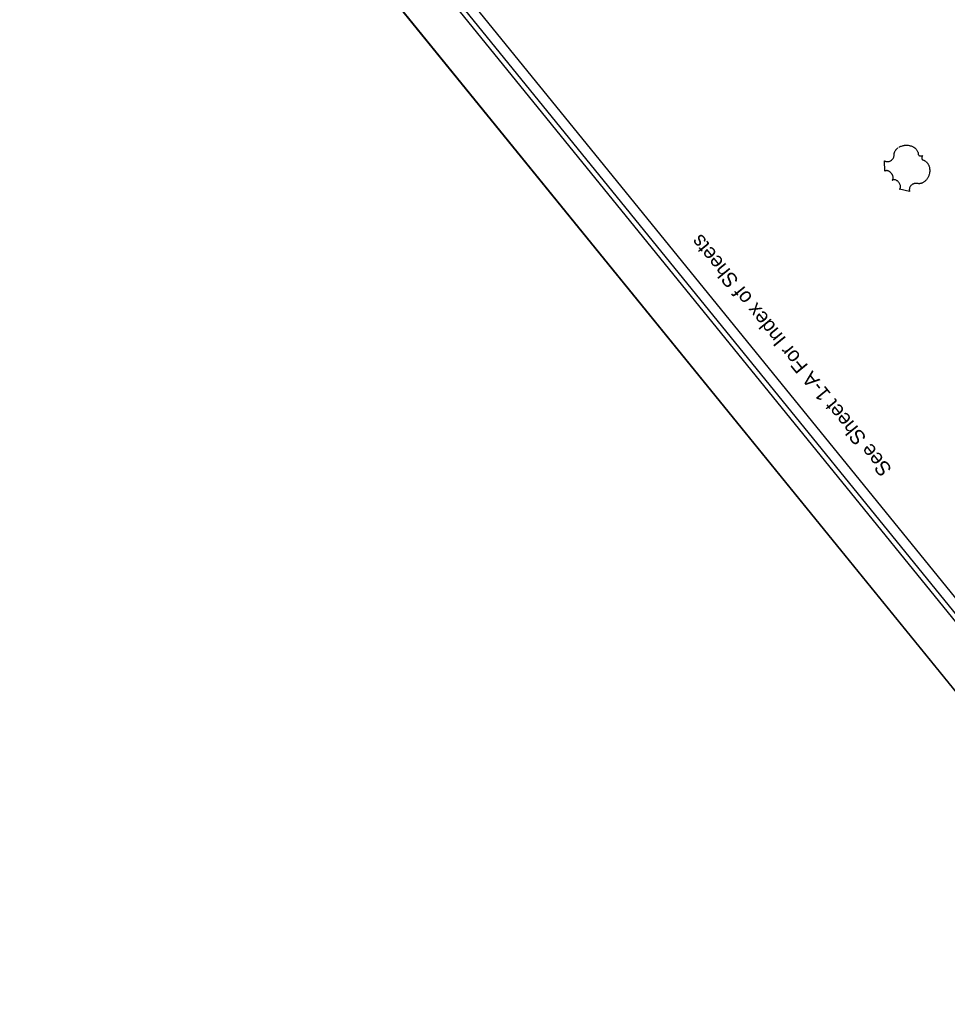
# Model space of a CAD drawing. Extents: x 2596486 to 2602076, y 851390 to 856110.
# Drawn here: x 2597251 to 2598058, y 851390 to 852253 of the extents above; entities that cross this region are included whole.
import ezdxf

# ---------------------------------------------------------------- set-up
doc = ezdxf.new("R2010")
doc.units = 0
for name, color, linetype in [('Default', 7, 'Continuous'), ('Sheet Cutting Line CELL', 7, 'Continuous'), ('Sheet Plot Border Inside CELL', 7, 'Continuous'), ('Sheet Plot Border Outside CELL', 7, 'Continuous'), ('Sheet Title CELL', 7, 'Continuous')]:
    doc.layers.add(name, color=color, linetype=linetype)

msp = doc.modelspace()

# ---------------------------------------------------------------- linework, layer by layer
at = {"layer": 'Default'}
for p, q in [((2598011.8, 852138.29), (2598011.93, 852138.61)), ((2598011.93, 852138.61), (2598012.05, 852138.88)), ((2598012.05, 852138.88), (2598012.36, 852139.46)), ((2598012.36, 852139.46), (2598012.7, 852139.97)), ((2598012.7, 852139.97), (2598012.89, 852140.23)), ((2598012.89, 852140.23), (2598013.34, 852140.77)), ((2598013.34, 852140.77), (2598013.58, 852141.02)), ((2598013.58, 852141.02), (2598014.07, 852141.49)), ((2598014.07, 852141.49), (2598014.7, 852142.01)), ((2598015.35, 852142.45), (2598016.14, 852142.91)), ((2598016.14, 852142.91), (2598016.64, 852143.16)), ((2598016.64, 852143.16), (2598017.25, 852143.41)), ((2598017.25, 852143.41), (2598017.78, 852143.62)), ((2598017.78, 852143.62), (2598018.61, 852143.88)), ((2598018.61, 852143.88), (2598019.25, 852144.02)), ((2598019.25, 852144.02), (2598020.01, 852144.17)), ((2598020.01, 852144.17), (2598020.49, 852144.23)), ((2598020.49, 852144.23), (2598021.03, 852144.28)), ((2598021.03, 852144.28), (2598021.66, 852144.31)), ((2598021.66, 852144.31), (2598022.35, 852144.32)), ((2598022.35, 852144.32), (2598023.12, 852144.27)), ((2598023.12, 852144.27), (2598023.72, 852144.21)), ((2598023.72, 852144.21), (2598024.45, 852144.1)), ((2598024.45, 852144.1), (2598024.87, 852144.01)), ((2598024.87, 852144.01), (2598025.45, 852143.87)), ((2598025.45, 852143.87), (2598026.2, 852143.64)), ((2598026.2, 852143.64), (2598026.89, 852143.37)), ((2598026.89, 852143.37), (2598027.46, 852143.12)), ((2598027.46, 852143.12), (2598027.92, 852142.88)), ((2598027.92, 852142.88), (2598028.5, 852142.54)), ((2598028.5, 852142.54), (2598029.38, 852141.92)), ((2598029.38, 852141.92), (2598029.69, 852141.67)), ((2598029.69, 852141.67), (2598030.02, 852141.36)), ((2598030.02, 852141.36), (2598030.32, 852141.06)), ((2598030.32, 852141.06), (2598030.6, 852140.76)), ((2598030.6, 852140.76), (2598030.95, 852140.33)), ((2598030.95, 852140.33), (2598031.26, 852139.88)), ((2598031.26, 852139.88), (2598031.53, 852139.43)), ((2598031.53, 852139.43), (2598031.78, 852138.94)), ((2598031.78, 852138.94), (2598032, 852138.4)), ((2598032, 852138.4), (2598032.17, 852137.88)), ((2598003.21, 852121.63), (2598003.12, 852130.67)), ((2598003.12, 852130.67), (2598003.28, 852130.58)), ((2598003.28, 852130.58), (2598003.67, 852130.4)), ((2598003.67, 852130.4), (2598004, 852130.28)), ((2598004, 852130.28), (2598004.57, 852130.11)), ((2598004.57, 852130.11), (2598004.85, 852130.07)), ((2598004.85, 852130.07), (2598005.13, 852130.03)), ((2598005.13, 852130.03), (2598005.42, 852130.02)), ((2598005.42, 852130.02), (2598005.68, 852130.01)), ((2598005.68, 852130.01), (2598006.02, 852130.03)), ((2598006.02, 852130.03), (2598006.36, 852130.07)), ((2598006.36, 852130.07), (2598006.72, 852130.12)), ((2598006.72, 852130.12), (2598007.01, 852130.19)), ((2598007.01, 852130.19), (2598007.59, 852130.38)), ((2598007.59, 852130.38), (2598007.93, 852130.53)), ((2598007.93, 852130.53), (2598008.21, 852130.67)), ((2598008.21, 852130.67), (2598008.75, 852131)), ((2598008.75, 852131), (2598009, 852131.18)), ((2598009, 852131.18), (2598009.23, 852131.36)), ((2598009.23, 852131.36), (2598009.46, 852131.57)), ((2598009.46, 852131.57), (2598009.68, 852131.79)), ((2598009.68, 852131.79), (2598009.89, 852132.03)), ((2598009.89, 852132.03), (2598010.07, 852132.24)), ((2598010.07, 852132.24), (2598010.28, 852132.52)), ((2598010.28, 852132.52), (2598010.5, 852132.86)), ((2598010.5, 852132.86), (2598010.7, 852133.22)), ((2598010.7, 852133.22), (2598010.97, 852133.86)), ((2598010.97, 852133.86), (2598011.2, 852134.58)), ((2598011.2, 852134.58), (2598011.28, 852135.03)), ((2598011.28, 852135.03), (2598011.33, 852135.45)), ((2598011.33, 852135.45), (2598011.34, 852136.02)), ((2598011.34, 852136.02), (2598011.36, 852136.33)), ((2598011.36, 852136.33), (2598011.39, 852136.71)), ((2598011.39, 852136.71), (2598011.51, 852137.38)), ((2598011.51, 852137.38), (2598011.59, 852137.67)), ((2598011.59, 852137.67), (2598011.69, 852137.99)), ((2598011.69, 852137.99), (2598011.8, 852138.29)), ((2598032.17, 852137.88), (2598032.3, 852137.31)), ((2598032.3, 852137.31), (2598032.42, 852136.29)), ((2598032.42, 852136.29), (2598032.48, 852136.01)), ((2598032.48, 852136.01), (2598032.54, 852135.87)), ((2598032.54, 852135.87), (2598032.74, 852135.6)), ((2598032.74, 852135.6), (2598032.99, 852135.4)), ((2598032.99, 852135.4), (2598033.3, 852135.23)), ((2598033.3, 852135.23), (2598033.5, 852135.14)), ((2598033.5, 852135.14), (2598033.8, 852135.04)), ((2598033.8, 852135.04), (2598034.05, 852134.99)), ((2598034.05, 852134.99), (2598034.38, 852134.95)), ((2598034.38, 852134.95), (2598034.64, 852134.94)), ((2598034.64, 852134.94), (2598034.83, 852134.93)), ((2598034.83, 852134.93), (2598035.29, 852134.99)), ((2598035.29, 852134.99), (2598035.49, 852135.04)), ((2598035.4, 852133.72), (2598035.37, 852133.41)), ((2598035.37, 852133.41), (2598035.37, 852133.07)), ((2598035.37, 852133.07), (2598035.42, 852132.74)), ((2598035.46, 852134.09), (2598035.4, 852133.72)), ((2598035.42, 852132.74), (2598035.47, 852132.49)), ((2598035.54, 852134.35), (2598035.46, 852134.09)), ((2598035.47, 852132.49), (2598035.54, 852132.28)), ((2598035.49, 852135.04), (2598035.73, 852135.11)), ((2598035.64, 852134.62), (2598035.54, 852134.35)), ((2598035.54, 852132.28), (2598035.65, 852132.04)), ((2598035.78, 852134.91), (2598035.64, 852134.62)), ((2598035.65, 852132.04), (2598035.77, 852131.87)), ((2598035.73, 852135.11), (2598036.05, 852135.27)), ((2598035.77, 852131.87), (2598035.88, 852131.74)), ((2598036.05, 852135.27), (2598035.78, 852134.91)), ((2598035.88, 852131.74), (2598036.07, 852131.59)), ((2598036.07, 852131.59), (2598036.45, 852131.48)), ((2598036.45, 852131.48), (2598036.81, 852131.38)), ((2598036.81, 852131.38), (2598037.17, 852131.25)), ((2598037.17, 852131.25), (2598037.58, 852131.08)), ((2598037.58, 852131.08), (2598037.87, 852130.94)), ((2598037.87, 852130.94), (2598038.19, 852130.76)), ((2598038.19, 852130.76), (2598038.54, 852130.53)), ((2598038.54, 852130.53), (2598038.91, 852130.27)), ((2598038.91, 852130.27), (2598039.26, 852129.98)), ((2598039.26, 852129.98), (2598039.55, 852129.71)), ((2598003.38, 852121.76), (2598003.21, 852121.63)), ((2598003.59, 852121.89), (2598003.38, 852121.76)), ((2598003.86, 852122.01), (2598003.59, 852121.89)), ((2598004.14, 852122.09), (2598003.86, 852122.01)), ((2598004.41, 852122.16), (2598004.14, 852122.09)), ((2598004.71, 852122.18), (2598004.41, 852122.16)), ((2598005.16, 852122.17), (2598004.71, 852122.18)), ((2598005.57, 852122.11), (2598005.16, 852122.17)), ((2598005.9, 852122.04), (2598005.57, 852122.11)), ((2598006.29, 852121.9), (2598005.9, 852122.04)), ((2598006.75, 852121.71), (2598006.29, 852121.9)), ((2598007.07, 852121.54), (2598006.75, 852121.71)), ((2598007.42, 852121.33), (2598007.07, 852121.54)), ((2598007.78, 852121.07), (2598007.42, 852121.33)), ((2598039.55, 852129.71), (2598039.85, 852129.41)), ((2598039.85, 852129.41), (2598040.1, 852129.12)), ((2598040.1, 852129.12), (2598040.34, 852128.81)), ((2598040.34, 852128.81), (2598040.55, 852128.5)), ((2598040.55, 852128.5), (2598040.8, 852128.15)), ((2598040.8, 852128.15), (2598041.07, 852127.68)), ((2598041.07, 852127.68), (2598041.27, 852127.27)), ((2598041.27, 852127.27), (2598041.47, 852126.83)), ((2598041.47, 852126.83), (2598041.66, 852126.37)), ((2598041.66, 852126.37), (2598041.83, 852125.84)), ((2598041.83, 852125.84), (2598042.02, 852125.17)), ((2598042.02, 852125.17), (2598042.12, 852124.68)), ((2598042.12, 852124.68), (2598042.25, 852123.87)), ((2598042.3, 852121.45), (2598042.19, 852120.5)), ((2598042.25, 852123.87), (2598042.33, 852122.87)), ((2598042.33, 852122.07), (2598042.3, 852121.45)), ((2598042.33, 852122.87), (2598042.33, 852122.07)), ((2598008.04, 852120.86), (2598007.78, 852121.07)), ((2598008.34, 852120.59), (2598008.04, 852120.86)), ((2598008.6, 852120.34), (2598008.34, 852120.59)), ((2598008.84, 852120.08), (2598008.6, 852120.34)), ((2598009.09, 852119.78), (2598008.84, 852120.08)), ((2598009.28, 852119.53), (2598009.09, 852119.78)), ((2598009.5, 852119.22), (2598009.28, 852119.53)), ((2598009.69, 852118.89), (2598009.5, 852119.22)), ((2598009.92, 852114.01), (2598009.6, 852113.78)), ((2598009.6, 852113.78), (2598009.84, 852114.01)), ((2598009.88, 852118.57), (2598009.69, 852118.89)), ((2598009.84, 852114.01), (2598009.98, 852114.16)), ((2598010.04, 852118.22), (2598009.88, 852118.57)), ((2598010.09, 852114.09), (2598009.92, 852114.01)), ((2598009.98, 852114.16), (2598010.1, 852114.33)), ((2598010.19, 852117.87), (2598010.04, 852118.22)), ((2598010.52, 852114.25), (2598010.09, 852114.09)), ((2598010.1, 852114.33), (2598010.21, 852114.53)), ((2598010.29, 852117.59), (2598010.19, 852117.87)), ((2598010.21, 852114.53), (2598010.35, 852114.84)), ((2598010.37, 852117.3), (2598010.29, 852117.59)), ((2598010.35, 852114.84), (2598010.44, 852115.13)), ((2598010.5, 852116.69), (2598010.37, 852117.3)), ((2598010.44, 852115.13), (2598010.53, 852115.61)), ((2598010.55, 852116.1), (2598010.5, 852116.69)), ((2598010.74, 852114.29), (2598010.52, 852114.25)), ((2598010.53, 852115.61), (2598010.55, 852115.87)), ((2598010.55, 852115.87), (2598010.55, 852116.1)), ((2598010.98, 852114.32), (2598010.74, 852114.29)), ((2598011.46, 852114.33), (2598010.98, 852114.32)), ((2598011.98, 852114.26), (2598011.46, 852114.33)), ((2598012.29, 852114.18), (2598011.98, 852114.26)), ((2598012.67, 852114.05), (2598012.29, 852114.18)), ((2598013.12, 852113.87), (2598012.67, 852114.05)), ((2598013.48, 852113.67), (2598013.12, 852113.87)), ((2598013.85, 852113.44), (2598013.48, 852113.67)), ((2598014.16, 852113.21), (2598013.85, 852113.44)), ((2598014.79, 852112.68), (2598014.16, 852113.21)), ((2598015.29, 852112.15), (2598014.79, 852112.68)), ((2598037.87, 852112.68), (2598037.5, 852112.39)), ((2598038.31, 852113.05), (2598037.87, 852112.68)), ((2598038.77, 852113.47), (2598038.31, 852113.05)), ((2598039.18, 852113.91), (2598038.77, 852113.47)), ((2598039.46, 852114.24), (2598039.18, 852113.91)), ((2598039.84, 852114.73), (2598039.46, 852114.24)), ((2598040.05, 852115.02), (2598039.84, 852114.73)), ((2598040.36, 852115.5), (2598040.05, 852115.02)), ((2598040.68, 852116.02), (2598040.36, 852115.5)), ((2598040.99, 852116.62), (2598040.68, 852116.02)), ((2598041.2, 852117.06), (2598040.99, 852116.62)), ((2598041.49, 852117.78), (2598041.2, 852117.06)), ((2598041.66, 852118.25), (2598041.49, 852117.78)), ((2598041.86, 852118.92), (2598041.66, 852118.25)), ((2598042.09, 852119.91), (2598041.86, 852118.92)), ((2598042.19, 852120.5), (2598042.09, 852119.91)), ((2598015.7, 852111.63), (2598015.29, 852112.15)), ((2598016.07, 852111.05), (2598015.7, 852111.63)), ((2598015.99, 852105.94), (2598016.21, 852106.14)), ((2598024.82, 852104.01), (2598015.99, 852105.94)), ((2598016.37, 852110.49), (2598016.07, 852111.05)), ((2598016.21, 852106.14), (2598016.43, 852106.41)), ((2598016.62, 852109.9), (2598016.37, 852110.49)), ((2598016.43, 852106.41), (2598016.54, 852106.57)), ((2598016.54, 852106.57), (2598016.7, 852106.91)), ((2598016.78, 852109.33), (2598016.62, 852109.9)), ((2598016.7, 852106.91), (2598016.85, 852107.37)), ((2598016.89, 852108.8), (2598016.78, 852109.33)), ((2598016.85, 852107.37), (2598016.92, 852107.92)), ((2598016.92, 852108.46), (2598016.89, 852108.8)), ((2598016.92, 852107.92), (2598016.92, 852108.46)), ((2598024.62, 852106.2), (2598024.58, 852105.76)), ((2598024.58, 852105.76), (2598024.59, 852105.38)), ((2598024.59, 852105.38), (2598024.61, 852105.02)), ((2598024.61, 852105.02), (2598024.67, 852104.61)), ((2598024.7, 852106.66), (2598024.62, 852106.2)), ((2598024.67, 852104.61), (2598024.75, 852104.23)), ((2598024.84, 852107.16), (2598024.7, 852106.66)), ((2598024.75, 852104.23), (2598024.82, 852104.01)), ((2598025.03, 852107.67), (2598024.84, 852107.16)), ((2598025.2, 852108.01), (2598025.03, 852107.67)), ((2598025.45, 852108.44), (2598025.2, 852108.01)), ((2598025.7, 852108.78), (2598025.45, 852108.44)), ((2598026, 852109.15), (2598025.7, 852108.78)), ((2598026.35, 852109.5), (2598026, 852109.15)), ((2598026.66, 852109.77), (2598026.35, 852109.5)), ((2598027.07, 852110.08), (2598026.66, 852109.77)), ((2598027.42, 852110.29), (2598027.07, 852110.08)), ((2598027.81, 852110.5), (2598027.42, 852110.29)), ((2598028.12, 852110.64), (2598027.81, 852110.5)), ((2598028.59, 852110.82), (2598028.12, 852110.64)), ((2598028.91, 852110.91), (2598028.59, 852110.82)), ((2598029.37, 852111.01), (2598028.91, 852110.91)), ((2598029.69, 852111.06), (2598029.37, 852111.01)), ((2598030.06, 852111.1), (2598029.69, 852111.06)), ((2598030.48, 852111.11), (2598030.06, 852111.1)), ((2598030.81, 852111.1), (2598030.48, 852111.11)), ((2598031.38, 852111.03), (2598030.81, 852111.1)), ((2598031.81, 852110.94), (2598031.38, 852111.03)), ((2598032.33, 852110.88), (2598031.81, 852110.94)), ((2598032.86, 852110.84), (2598032.33, 852110.88)), ((2598033.31, 852110.85), (2598032.86, 852110.84)), ((2598033.81, 852110.9), (2598033.31, 852110.85)), ((2598034.25, 852110.97), (2598033.81, 852110.9)), ((2598034.76, 852111.09), (2598034.25, 852110.97)), ((2598035.27, 852111.24), (2598034.76, 852111.09)), ((2598035.7, 852111.4), (2598035.27, 852111.24)), ((2598036.05, 852111.55), (2598035.7, 852111.4)), ((2598036.51, 852111.78), (2598036.05, 852111.55)), ((2598037.03, 852112.08), (2598036.51, 852111.78)), ((2598037.5, 852112.39), (2598037.03, 852112.08))]:
    msp.add_line(p, q, dxfattribs=at)
at = {"layer": 'Sheet Cutting Line CELL'}
msp.add_line((2598291.52, 851390.23), (2596485.91, 853611.8), dxfattribs=at)
at = {"layer": 'Sheet Plot Border Inside CELL'}
msp.add_lwpolyline([(2599699.12, 852562.74), (2597912.27, 854761.23), (2596520.36, 853629.94), (2598307.2, 851431.45)], close=True, dxfattribs=at)
at = {"layer": 'Sheet Plot Border Outside CELL'}
msp.add_lwpolyline([(2596485.91, 853611.8), (2598291.52, 851390.23), (2599742.65, 852569.65), (2597937.05, 854791.22)], close=True, dxfattribs=at)
at = {"layer": 'Sheet Title CELL'}
for points in [[(2596547.83, 853603.01), (2598134.72, 851650.5)], [(2596559.8, 853601.75), (2598082.33, 851728.47)]]:
    msp.add_lwpolyline(points, dxfattribs=at)

# ---------------------------------------------------------------- texts
msp.add_text('See Sheet 1-A For Index of Sheets', height=12.75, rotation=129.10281, dxfattribs=at).set_placement((2598010.09, 851862.73))

doc.saveas('drawing.dxf')
